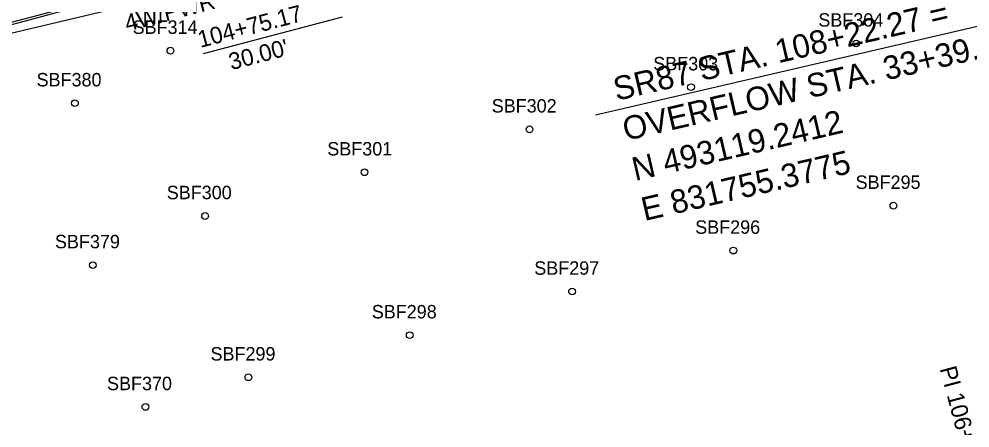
# Model space of a CAD drawing. Extents: x 818717 to 846077, y 440014 to 541392.
# Drawn here: x 831333.4 to 831616.5, y 492854.7 to 492976.5 of the extents above; entities that cross this region are included whole.
import ezdxf

# ---------------------------------------------------------------- set-up
doc = ezdxf.new("R2010")
doc.units = 0
for name, color, linetype in [('SURVEY - CENTERLINE - Preliminary Curve Text', 7, 'Continuous'), ('SURVEY - CENTERLINE - Preliminary Text', 7, 'Continuous'), ('SURVEY - DTM - Breaklines', 7, 'Continuous'), ('SURVEY - DTM - Spot Points - Locators', 7, 'Continuous'), ('SURVEY - DTM - Spot Points - Point Numbers', 7, 'Continuous'), ('SURVEY - PROPERTY - ROW Lines', 7, 'Continuous'), ('SURVEY - PROPERTY - Station and Offset Flags', 7, 'Continuous'), ('SURVEY - UTILITIES - Electric (Overhead) with Text', 7, 'Continuous')]:
    doc.layers.add(name, color=color, linetype=linetype)

msp = doc.modelspace()

# ---------------------------------------------------------------- linework, layer by layer
at = {"layer": 'SURVEY - CENTERLINE - Preliminary Text'}
msp.add_line((831505.04, 492947.98), (831661.86, 492984.41), dxfattribs=at)
at = {"layer": 'SURVEY - DTM - Breaklines'}
msp.add_lwpolyline([(831183.26, 492932.89), (831228.9, 492946.86), (831278.55, 492959.55), (831323.37, 492970.48), (831362.8, 492979.81)], dxfattribs=at)
at = {"layer": 'SURVEY - DTM - Spot Points - Locators'}
for centre in [(831582.58, 492969.23), (831378.48, 492967.08), (831533.44, 492956.21), (831350.07, 492951.43), (831485.36, 492943.65), (831436.27, 492930.86), (831593.67, 492920.91), (831388.81, 492917.83), (831546.04, 492907.53), (831355.38, 492903.21), (831498.03, 492895.33), (831449.71, 492882.33), (831401.69, 492869.79), (831371.04, 492860.96)]:
    msp.add_circle(centre, 1, dxfattribs=at)
at = {"layer": 'SURVEY - PROPERTY - ROW Lines'}
msp.add_line((830967.99, 492880.22), (831427.58, 493000.93), dxfattribs=at)
at = {"layer": 'SURVEY - PROPERTY - Station and Offset Flags'}
msp.add_line((831429.62, 492977.03), (831388.28, 492966.17), dxfattribs=at)
at = {"layer": 'SURVEY - UTILITIES - Electric (Overhead) with Text'}
msp.add_lwpolyline([(832667.18, 493331.74), (832415.28, 493266.23), (832147.85, 493195.27), (831907.96, 493131.64), (831666.03, 493064.14), (831375.19, 492986.65), (831101.3, 492913.04)], dxfattribs=at)

# ---------------------------------------------------------------- texts
at = {"layer": 'SURVEY - CENTERLINE - Preliminary Curve Text'}
msp.add_text('PI 106+18.40', height=5, rotation=284.8795, dxfattribs=at).set_placement((831607.43, 492872.39))
at = {"layer": 'SURVEY - CENTERLINE - Preliminary Text'}
for s, p in [('SR87 STA. 108+22.27 =', (831511.26, 492952.12)), ('OVERFLOW STA. 33+39.09', (831514.03, 492940.19)), ('N 493119.2412', (831516.81, 492928.25)), ('E 831755.3775', (831519.58, 492916.32))]:
    msp.add_text(s, height=7, rotation=13.0771, dxfattribs=at).set_placement(p)
at = {"layer": 'SURVEY - DTM - Spot Points - Point Numbers'}
for s, p in [('SBF304', (831571.34, 492974.23)), ('SBF314', (831367.24, 492972.08)), ('SBF303', (831522.2, 492961.21)), ('SBF380', (831338.66, 492956.43)), ('SBF302', (831474.12, 492948.65)), ('SBF301', (831425.19, 492935.86)), ('SBF295', (831582.43, 492925.91)), ('SBF300', (831377.4, 492922.83)), ('SBF296', (831534.69, 492912.53)), ('SBF379', (831344.13, 492908.21)), ('SBF297', (831486.79, 492900.33)), ('SBF298', (831438.42, 492887.33)), ('SBF299', (831390.43, 492874.79)), ('SBF370', (831359.63, 492865.96))]:
    msp.add_text(s, height=4, dxfattribs=at).set_placement(p)
at = {"layer": 'SURVEY - PROPERTY - Station and Offset Flags'}
for s, p in [('104+75.17', (831387.39, 492967.88)), ("30.00'", (831396.61, 492961.25))]:
    msp.add_text(s, height=5, rotation=14.7154, dxfattribs=at).set_placement(p)
at = {"layer": 'SURVEY - UTILITIES - Electric (Overhead) with Text'}
msp.add_text('4W/PWR', height=5, rotation=14.7154, dxfattribs=at).set_placement((831365.62, 492972.73))

doc.saveas('drawing.dxf')
